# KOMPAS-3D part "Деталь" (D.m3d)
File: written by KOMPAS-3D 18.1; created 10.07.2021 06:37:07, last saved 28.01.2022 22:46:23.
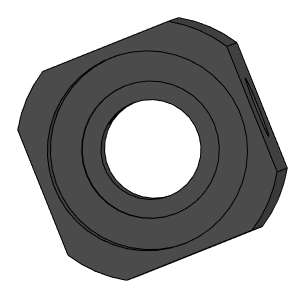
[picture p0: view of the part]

Document properties: Автор: 111; Полное имя файла: C:\Users\admin\Desktop\ffb\D.m3d

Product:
- Part/product: Деталь
    Масса: 0.194146
    source file: ..\1.cdw, 6.cdw

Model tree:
1. Эскиз:1
2. Элемент выдавливания:1
     Расстояние 1 = 40
3. Эскиз:2
4. Элемент выдавливания:2
     Расстояние 2 = -10
5. Эскиз:3
6. Элемент выдавливания:3
     Расстояние 2 = -40
7. Эскиз:7
8. Элемент выдавливания:4
     Расстояние 1 = -30; Смещение 2 = 30
9. Эскиз:8
10. Элемент выдавливания:5
     Расстояние 2 = 21
11. Эскиз:9
12. Элемент выдавливания:6
     Расстояние 2 = 21
13. Эскиз:10
14. Элемент выдавливания:10
     Расстояние 2 = -40
15. Эскиз:11  (with: Элемент выдавливания:10)
16. Эскиз:12  (with: Элемент выдавливания:4)
17. Элемент выдавливания:11
     Расстояние 2 = 2
18. Элемент выдавливания:12  (with: Элемент выдавливания:2)
     Расстояние 2 = 2
19. Эскиз:13  (with: Элемент выдавливания:12)
20. Элемент выдавливания:13
     Расстояние 2 = 2

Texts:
  Точка начала. Х
  Точка начала. Y
  Точка начала. Z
